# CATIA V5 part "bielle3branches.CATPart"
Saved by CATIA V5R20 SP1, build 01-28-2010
Part number: bielle3branches
Bounding box of the stored display mesh (mm): x 0 to 20, y 21.892 to 135.815, z -20.951 to 79.049
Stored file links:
  E:\EDELI\gcausse\Edeli_2012_613_gcausse\bielle3branches.CATPart
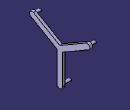
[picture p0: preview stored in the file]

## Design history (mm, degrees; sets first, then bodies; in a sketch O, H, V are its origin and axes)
Set1 "croix"
  DatumSurface1
  Sketch1 on face of DatumSurface1, origin (15, 0, 0), H (0, 1, 0), V (0, 0, 1)
    line L1 (78.8534, 44.049) -> (26.8919, 74.049)
    point P1 (78.8534, 44.049)
    point P2 (26.8919, 74.049)
    line L2 (78.8534, 44.049) -> (130.815, 74.049)
    line L3 (78.8534, 44.049) -> (78.8534, -15.951)
    point P4 (78.8534, -15.951)
    length L2 = 60
    length L1 = 60
    length L3 = 60
    angle L2 L3 = 120
    angle L3 L1 = 120
    vertical: L3 V
Set2 "axe"
  Line1: type PtDir, RefPoint Sketch1.P1, Direction edge [face of Pad1 from Sketch2.L1 | face of Pad1 from Sketch2.L2], Start 0, End 20
Body1 (main body)
  DatumSurface2
Body2
  DatumSurface3
  Sketch2 on face of DatumSurface3, origin (15, 0, 0), H (0, 1, 0), V (0, 0, 1)
    line L1 (133.315, 69.7189) -> (83.8534, 41.1623)
    line L2 (83.8534, 41.1623) -> (83.8534, -15.951)
    arc A1 centre (78.8534, -15.951) radius 5 from (83.8534, -15.951) to (73.8534, -15.951) cw
    point P4 (78.8534, -15.951)
    line L3 (73.8534, -15.951) -> (73.8534, 41.1623)
    line L4 (73.8534, 41.1623) -> (24.3919, 69.7189)
    arc A2 centre (26.8919, 74.049) radius 5 from (24.3919, 69.7189) to (29.3919, 78.3792) cw
    point P8 (26.8919, 74.049)
    line L5 (29.3919, 78.3792) -> (78.8534, 49.8225)
    line L6 (78.8534, 49.8225) -> (128.315, 78.3792)
    arc A3 centre (130.815, 74.049) radius 5 from (128.315, 78.3792) to (133.315, 69.7189) cw
    point P12 (130.815, 74.049)
    reference projected line E1 (78.8534, 44.049) -> (130.815, 74.049) from Sketch1.L2
    reference projected line E2 (78.8534, 44.049) -> (130.815, 74.049) from Sketch1.L2
    reference projected line E3 (78.8534, 44.049) -> (26.8919, 74.049) from Sketch1.L1
    reference projected line E4 (78.8534, 44.049) -> (26.8919, 74.049) from Sketch1.L1
    reference projected line E5 (78.8534, 44.049) -> (78.8534, -15.951) from Sketch1.L3
    reference projected line E6 (78.8534, 44.049) -> (78.8534, -15.951) from Sketch1.L3
    reference projected point E7 (78.8534, 44.049) from Sketch1.P1
    reference projected point E8 (26.8919, 74.049) from Sketch1.P2
    reference projected point E9 (78.8534, -15.951) from Sketch1.P4
    distance P12 E7 = 60
    distance L6 L1 = 10
    distance L5 L4 = 10
    distance L2 L3 = 10
    vertical: L2 V
    tangency: A1 L2, L3 A1, A2 L4, A3 L6, A3 L1
    parallelism: L1 E1, L4 E3, L3 E5
    symmetry: L6 L1 E2, L5 L4 E4, L2 L3 E6
    coincidence: P8 E8, P4 E9
  Pad1: profile Sketch2, direction (1, 0, 0), length 5
  Sketch3 on start face of Pad1, origin (15, 0, 0), H (0, -1, 0), V (0, 0, 1)
    circle A1 centre (-130.815, 74.049) radius 2.5
    reference projected arc E1 centre (-130.815, 74.049) radius 5 from (-128.315, 78.3792) to (-133.315, 69.7189) ccw from edge [start face of Pad1 | face of Pad1 from Sketch2.A3]
    reference projected arc E2 centre (-130.815, 74.049) radius 5 from (-128.315, 78.3792) to (-133.315, 69.7189) ccw from edge [start face of Pad1 | face of Pad1 from Sketch2.A3]
    circle A2 centre (-26.8919, 74.049) radius 2.5
    reference projected arc E3 centre (-26.8919, 74.049) radius 5 from (-24.3919, 69.7189) to (-29.3919, 78.3792) ccw from edge [start face of Pad1 | face of Pad1 from Sketch2.A2]
    reference projected arc E4 centre (-26.8919, 74.049) radius 5 from (-24.3919, 69.7189) to (-29.3919, 78.3792) ccw from edge [start face of Pad1 | face of Pad1 from Sketch2.A2]
    reference projected arc E5 centre (-78.8534, -15.951) radius 5 from (-83.8534, -15.951) to (-73.8534, -15.951) ccw from edge [start face of Pad1 | face of Pad1 from Sketch2.A1]
    radius A1 = 2.5
    radius E2 = 5 (reference)
    radius A2 = 2.5
    radius E4 = 5 (reference)
    radius E5 = 5 (reference)
    concentricity: A1 E1, A2 E3
  Pad2: profile Sketch3, direction (-1, 0, 0), length 10
  Sketch4 on start face of Pad1, origin (15, 0, 0), H (0, -1, 0), V (0, 0, 1)
    circle A1 centre (-78.8534, -15.951) radius 2.5
    reference projected arc E1 centre (-78.8534, -15.951) radius 5 from (-83.8534, -15.951) to (-73.8534, -15.951) ccw from edge [start face of Pad1 | face of Pad1 from Sketch2.A1]
    reference projected arc E2 centre (-78.8534, -15.951) radius 5 from (-83.8534, -15.951) to (-73.8534, -15.951) ccw from edge [start face of Pad1 | face of Pad1 from Sketch2.A1]
    radius A1 = 2.5
    radius E2 = 5 (reference)
    concentricity: A1 E1
  Pad3: profile Sketch4, direction (-1, 0, 0), length 15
